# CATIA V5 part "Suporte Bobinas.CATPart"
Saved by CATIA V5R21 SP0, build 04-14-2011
Part number: Suporte Bobinas
Definition: Suporte Bobinas
Nomenclature: Suporte Bobinas
Source: Unknown
Bounding box of the stored display mesh (mm): x -3.964 to 4, y -7.5 to 1, z -3.866 to 3.86
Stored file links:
  C:\Users\beatr\OneDrive\Documents\UNB\2026_1\Pi1\Componentes eletronicos\Suporte Bobinas.CATPart
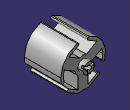
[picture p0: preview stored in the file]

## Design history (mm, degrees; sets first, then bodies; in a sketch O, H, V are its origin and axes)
Body1 "Sólido1" (main body)
  Solid1: solid without history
